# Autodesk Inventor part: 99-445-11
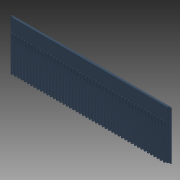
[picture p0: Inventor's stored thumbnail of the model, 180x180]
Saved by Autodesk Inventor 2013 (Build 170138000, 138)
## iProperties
Created: 2004-11
Part Number: 99-445-11
Document SubType Name: Modeling
Designer: Autodesk, Inc.
Manufacturer: Standard
Standards Organization: Custom
Description: TOTE, SLOTTED DIVIDER, SHORT
Mass: 64.8975 g
Surface Area: 497.9 cm^2
Volume: 64.8975 cm^3
Density: 1 g/cm^3
Material: Allgemein
CAGE: 1LJX3
Dept. ID: Product Design
Description #2: ---
Finish #1: ---
Finish #2: ---
Material ID: ---
Project Number: ---
Author: Autodesk, Inc.
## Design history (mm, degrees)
sketch "Sketch1"
  geometry: L1 (-120, 37.5)-(120, 37.5); L2 (120, 37.5)-(120, -37.5); L3 (120, -37.5)-(-120, -37.5); L4 (-120, -37.5)-(-120, 37.5); 3 further points
  constraints: 8 end point, 2 midpoint, 2 parallel, 1 horizontal, 1 horizontal alignment, 1 perpendicular, 1 vertical alignment
  dimensions: "d0" = 75 distance of L3.end L1.start; "d1" = 240 distance of L1.start L1.end
extrude "Extrusion1" new body sketch "Sketch1" distance "d2" = 3; taper "d3" = 0 deg
sketch "Sketch2"
  geometry: L1 (120, -37.5)-(-120, -37.5) reference; L2 (-120, -37.5)-(-120, 10); L3 (-120, 10)-(-119.375, 17.5); L4 (-119.375, 17.5)-(-118.625, 17.5); L5 (-118.625, 17.5)-(-118, 10); L6 (-118, 10)-(-118, -37.5); L7 (-119, 17.5)-(-119, -37.5); L8 (-120, -37.5)-(-120, 37.5) reference; L9 (-120, 37.5)-(120, 37.5) reference
  constraints: 12 end point, 4 perpendicular, 3 point on line, 1 collinear, 1 midpoint, 2 other
  dimensions: "d4" = 2 distance between parallel lines of L6 L2; "d5" = 0.75 distance of L3.end L4.end; "d15" = 7.5 distance from line of L2.end L4; "d16" = 20 distance between parallel lines of L9 L4
extrude "Extrusion2" join sketch "Sketch2" distance "d8" = 2; taper "d9" = 0 deg
sketch "Sketch3"
  geometry: L1 (0, 0)-(-5, 0) reference; L2 (0, 75)-(0, 0) reference; L3 (0, 75)-(-3, 75) reference; L4 (-1.5, 75)-(-1.5, 0)
  constraints: 2 end point, 1 midpoint, 1 parallel, 1 point on line
extrude "Extrusion3" join sketch "Sketch3" distance "d13" = 3.5; taper "d14" = 0 deg
mirror "Mirror1"
body "Solid1"
pattern_linear "Rectangular Pattern1" dims "d12" = 5
